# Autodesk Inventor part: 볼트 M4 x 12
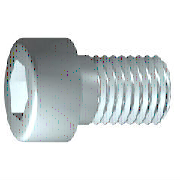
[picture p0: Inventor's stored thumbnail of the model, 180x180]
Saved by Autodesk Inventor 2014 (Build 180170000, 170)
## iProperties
IsCustomPart: 0
Created: 2012-02
Part Number: 볼트 M4 x 12
Material: 강철, 연강
Description: 6각 소켓 머리 캡 나사
Document SubType Name: Modeling
Standard: ISO 4762
Designer: mduedu
Standard Revision: Fourth edition 2004-03-01
Standards Organization: ISO
Language: ko-KR
Size Designation: M4 x 12
Categories: <MemberInstance><Categories><Category DisplayName="조임쇠" InternalName="e4da775c-781d-43d5-af7c-5136215cf5a6" Mnemonic="FSTN"><Category DisplayName="볼트" InternalN
Density: 7.75 g/cm^3
Appearance: Steel
Author: mduedu
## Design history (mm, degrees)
sketch "스케치1"
  geometry: L1 (-1, 0)-(12, 0); L2 (12, 0)-(12, 2); L3 (12, 2)-(1.75, 2); L4 (1.75, 2)-(1.32, 2); L5 (1.32, 2)-(0, 2); L6 (0, 2)-(0, 3.5); L7 (0, 3.5)-(-4, 3.5); L8 (-4, 3.5)-(-4, 1.732); L9 (-4, 1.732)-(-2, 1.732); L10 (-2, 1.732)-(-1, 0); L11 (-7.2, 0)-(15.2, 0) reference; L12 (0, -0.7)-(0, 4.2) reference; L13 (1.75, 2)-(0, 2)
  constraints: 22 end point, 6 parallel, 2 collinear, 2 perpendicular, 1 horizontal, 1 point on line
  dimensions: "d1" = 10.25 distance from line of L3.end L2 (= GEL); "d2" = 0.42952 distance of L4.end L3.end (computed from GAL); "d3" = 4 distance between parallel lines of L8 L6 (= KOH); "d4" = 2 distance of L8.end L9.end (= INTI); "d5" = 60 deg angle of L10 L1; "d6" = 4 diameter of L3 L1 (= GD); "d7" = 4 diameter of L5 L1 (= BDM); "d8" = 3.4641 diameter of L9 L1 (= 1.1547 x SW); "d9" = 7 diameter of L7 L1 (= KOD); "d26" = 12 distance between parallel lines of L12 L2 (= NLG)
revolve "본체" sketch "스케치1" stored, may be unused: angle "d10" = 90 deg
sketch "스케치2"
  geometry: L1 (0, -4.9)-(0, 4.9) reference; L2 (-4.9, 0)-(4.9, 0) reference; L3 (1.732, 0)-(0.866, -1.5); L4 (0.866, -1.5)-(-0.866, -1.5); L5 (-0.866, -1.5)-(-1.732, 0); L6 (-1.732, 0)-(-0.866, 1.5); L7 (-0.866, 1.5)-(0.866, 1.5); L8 (0.866, 1.5)-(1.732, 0); 2 further points
  constraints: 12 end point, 1 coincident, 1 horizontal alignment, 1 point on line, 12 other
extrude "슬롯" join sketch "스케치2" stored distance "d11" = 10; taper "d12" = 0 deg
workplane "Work Plane1"
fillet "Fillet2" dims "d30" = 0.1 (= R)
body "Solid1"
fillet "모깎기1" dims "d17" = 0.4 (= RR)
feature "스레드" dims "d13" = 10.25 (= GEL), "d14" = 0
chamfer "모따기1" distance "d15" = 0.42941 (= -0.5 x SPD + 0.5 x GD); stored, may be unused: second distance "d16" = 0.42941 (= GUL), angle "d27" = 45 deg
other parameters: "GD" = 4 [user parameter; used in 2 equation terms], "NLG" = 12 [user parameter; used in 1 equation term], "GEL" = 10.25 [user parameter; used in 2 equation terms], "KOD" = 7 [user parameter; used in 1 equation term], "KOH" = 4 [user parameter; used in 1 equation term], "INTI" = 2 [user parameter; used in 1 equation term], "GAL" = 0.42941 (= 0.61345 x PTC) [user parameter; used in 1 equation term], "GUL" = 0.42941 (= 0.61345 x PTC) [user parameter; used in 1 equation term], "BDM" = 4 (= NND) [user parameter; used in 1 equation term], "SW" = 3 [user parameter; used in 2 equation terms], "RR" = 0.4 [user parameter; used in 1 equation term], "SPD" = 3.14117 (= NND - 1.2269 x PTC) [user parameter; used in 1 equation term], "d19" = 0, "d28" = 0, "d29" = 0, "R" = 0.1 [user parameter; used in 1 equation term], "TOA" = 30 deg [user parameter], "GD1" = 3.14117 (= THREADDIA - 1.2269 x PTC) [user parameter], "THREADDIA" = 4 [user parameter; used in 1 equation term], "FAWI" = 45 deg [user parameter], "TPU" = 14.28571 (computed from PTC) [user parameter], "PTC" = 0.7 [user parameter; used in 5 equation terms], "NND" = 4 [user parameter; used in 2 equation terms], "E0" = 3.465 (= 1.155 x SW) [user parameter]
